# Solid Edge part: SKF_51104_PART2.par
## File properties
Title: SKF_51104_PART2
Author: psAdmin
Comments: Thrust ball bearings, single direction
Template: iso metric part.par
Last saved by: psAdmin
Revision: 1
Application: Solid Edge
Document Number: SKF_51104_PART2
Company: SKF
Density: 2,19430080538e+04 kg/m^3
Accuracy: 0,990
NB: SKF_51104_PART2
NT: Thrust ball bearings, single direction
NBSYN: SKF_$TC._PART2
LINA: SKF_51104_PART2
CATALOG: SKF
DESIGNATION: 51104
WASHER: No seat washer
DD: 20.0
D: 35.0
H: 10.00
LOAD1: 15.1
LOAD2: 29.0
LOAD3: 1.1
SPEED1: 7500
SPEED2: 10000
BEARING: 51104
SUPPLIER: SKF
ARTICLENO: SKF_51104_PART2
BOMINFO: SKF_51104_PART2
CREATOR: CADENAS GmbH
ID: skf:SKF_51104_PART2
CADENASIDSTR: DOCATTR{IDENT{"{$CADENAS_DATA/23d-libs/skf/bearings_units_and_housings/ball_bearings/thrust_ball_bearings/bd1_001_bdc_001.prj},207 {VTYP=3D},{NB=SKF_51104_PART2},{LINA=SKF_51104_PART2},{NN=BD1_001_BDC_001_PART2},{NOPRJ=TRUE},{DATE=08.09.2023 08:50:36},{GEOMDATE=04.09.2023 08:34:44},{VERSION=},{LINEID=46530},{WBVAR=WASHER},{WBNUMERIC=}  {NB=SKF_51104_PART2},{LINA=SKF_51104_PART2},{KT=DUMMY},{DESIGNATION=51104},{WASHER=},{DD=20.0},{D=35.0},{DX=},{DXX=MIN},{H=10.00},{H1=},{DD1=35.00},{D1=21.00},{D2=},{D3=},{C=},{R=},{SS=},{R12=0.3},{PITCH=27.500},{DW=5.556},{ALPHA=90},{DAMIN=29.00},{DAMAX=26.00},{RAMAX=0.30},{LOAD1=15.1},{LOAD2=29.0},{LOAD3=1.1},{SPEED1=7500},{SPEED2=10000},{A=0.0044},{Z=14},{II=1},{MASS=0.03700},{BEARING=51104},{WASHERVAR=},{POPULAR=Yes},{XHO=7.2224},{BHO=2.7776},{BSH=2.7776},{Y3=0},{H3=0},{B3=0},{WASHERALG='','No seat washer'},{WSPN=},{DESIGN=tbb1},{H1ALG=0},{SSALG=0},{RALG=0},{TC=51104},{DXA=35.000}"}}
Username: psAdmin
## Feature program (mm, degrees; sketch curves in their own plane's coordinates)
sketch for "unnamed RevolvedProtrusion 1" plane through (0, 0, 0) normal (0, 0, 1) x-axis (1, 0, 0)
revolve "unnamed RevolvedProtrusion 1" add finite 360 deg about sketch line (2.7776, 0) -> (0, 0)
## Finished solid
Body 1: solid body, 9 faces, 9 edges, 0 vertices.
  Faces by surface: torus 4, plane 3, cylinder 2
  Edges by curve: circle 9
Bounding box of the edges (mm; curved faces can reach further): 2.778 x 35.000 x 35.000, from (0, -17.5, -17.5) to (2.7776, 17.5, 17.5).
Cylindrical faces by radius (mm): R10 x1, R17.5 x1
Toroidal faces (ring radius, tube radius in mm): R10.3 r0.3 x2, R13.75 r2.778 x1, R17.2 r0.3 x1
Planar faces by outward normal: +x 2, -x 1
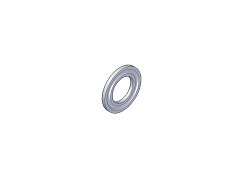
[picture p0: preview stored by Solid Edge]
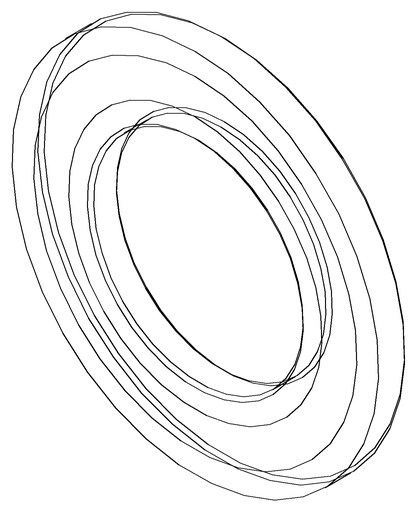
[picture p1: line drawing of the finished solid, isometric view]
